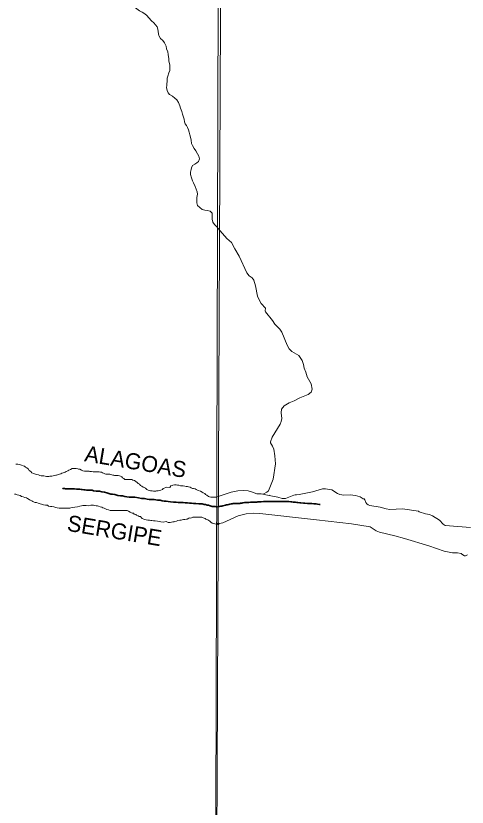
# Model space of a CAD drawing. Extents: x 553962 to 842807, y 8883888 to 9032388.
# Drawn here: x 595557 to 597811, y 8902976 to 8906931 of the extents above; entities that cross this region are included whole.
import ezdxf
from ezdxf.enums import TextEntityAlignment as Align

# ---------------------------------------------------------------- set-up
doc = ezdxf.new("R2010")
doc.units = 0
doc.header["$LTSCALE"] = 20
doc.header["$PDMODE"] = 32
doc.header["$PDSIZE"] = 10
doc.linetypes.add('LONG_DASH_SHORT_DASH', pattern=[9.9, 6, -1.2, 1.5, -1.2])
doc.layers.add('6', color=7, linetype='Continuous', lineweight=13)

msp = doc.modelspace()

# ---------------------------------------------------------------- linework, layer by layer
at = {"layer": '6'}
msp.add_line((597009.34, 8905170.59), (597009.47, 8905170.48), dxfattribs=at)
for points in [[(596655.53, 8924715.82), (596593.31, 8909930.27), (596531.66, 8896026.67)], [(596271.31, 8906832.67), (596268.84, 8906840.55), (596267.4, 8906852.57), (596265.95, 8906863.59), (596262.5, 8906875.62), (596254.54, 8906886.17), (596246.07, 8906895.23), (596235.12, 8906906.3), (596222.17, 8906920.38), (596211.22, 8906932.45), (596201.25, 8906941.01), (596187.27, 8906949.09), (596175.29, 8906955.66), (596161.83, 8906966.24), (596149.85, 8906973.81), (596139.89, 8906984.37), (596128.44, 8906996.94), (596121.49, 8907009.99), (596118.04, 8907020.52), (596117.51, 8907024.23)], [(596279.74, 8906816.97), (596272.29, 8906829.53), (596271.31, 8906832.67)], [(596461.16, 8906005.39), (596461.24, 8906022.7), (596463.82, 8906039.2), (596463.38, 8906051.22), (596457.43, 8906065.27), (596453.49, 8906078.3), (596444.56, 8906095.36), (596439.11, 8906106.91), (596433.67, 8906120.95), (596429.75, 8906138.49), (596429.79, 8906149), (596432.86, 8906162), (596433.9, 8906171.5), (596439.46, 8906181.98), (596451, 8906189.93), (596461.04, 8906195.39), (596470.08, 8906202.35), (596474.15, 8906216.84), (596471.21, 8906229.37), (596464.25, 8906241.42), (596455.81, 8906255.98), (596447.86, 8906268.03), (596439.92, 8906282.59), (596434.46, 8906292.63), (596433.04, 8906308.65), (596429.1, 8906323.69), (596426.15, 8906335.22), (596422.71, 8906348.75), (596419.27, 8906361.78), (596413.82, 8906373.32), (596408.85, 8906382.36), (596403.39, 8906390.89), (596399.93, 8906400.42), (596396.99, 8906413.45), (596393.55, 8906428.99), (596389.6, 8906440.02), (596386.16, 8906452.55), (596379.72, 8906468.6), (596376.28, 8906481.63), (596368.85, 8906497.18), (596361.4, 8906511.24), (596351.43, 8906519.3), (596339.97, 8906529.37), (596323.99, 8906537.46), (596317.29, 8906546.27), (596312.87, 8906557.64), (596309.71, 8906572.8), (596310.97, 8906582.91), (596310.72, 8906590.58), (596312.78, 8906603.09), (596313.36, 8906618.6), (596316.91, 8906629.09), (596321.49, 8906645.08), (596325.55, 8906657.57), (596326.12, 8906673.59), (596325.68, 8906686.1), (596321.76, 8906703.64), (596321.31, 8906715.66), (596317.41, 8906737.2), (596316.47, 8906750.72), (596310.03, 8906765.77), (596307.1, 8906779.79), (596300.17, 8906796.35), (596291.21, 8906807.91), (596279.74, 8906816.97)], [(596838.8, 8905408.88), (596804.04, 8905452.18), (596802.59, 8905456.77), (596803.35, 8905469.92), (596782.84, 8905493.91), (596770.59, 8905515.48), (596764.74, 8905530.23), (596754.34, 8905581.41), (596745.9, 8905609.64), (596737.38, 8905621.24), (596722.76, 8905631.69), (596710.55, 8905646.03), (596672.05, 8905729.1), (596650.19, 8905765.77), (596633.55, 8905797.37), (596611.19, 8905818.62), (596577.44, 8905855.54), (596559.67, 8905877.53), (596548.71, 8905888.6), (596540.25, 8905900.15), (596538.31, 8905914.18), (596537.89, 8905930.7), (596537.46, 8905945.22), (596526.99, 8905955.28), (596513.49, 8905957.86), (596500.49, 8905959.43), (596486.99, 8905962.5), (596476.02, 8905972.57), (596464.56, 8905983.14), (596461.12, 8905995.67), (596461.16, 8906005.39)], [(596792.7, 8904540.08), (596811.38, 8904551.14), (596818.41, 8904557.45), (596822.73, 8904565.46), (596841.54, 8904615.86), (596853.21, 8904691.81), (596850.74, 8904732.66), (596845.07, 8904764.51), (596839.3, 8904780.99), (596829.44, 8904796.54), (596828.87, 8904802.18), (596837.09, 8904824.68), (596877.08, 8904890.71), (596882.77, 8904903.43), (596885.53, 8904918.02), (596882.53, 8904946.28), (596884.25, 8904964.46), (596897.92, 8904981.99), (596922.55, 8904996.59), (596946.53, 8905006.22), (596975.28, 8905021.53), (597017.52, 8905037.76), (597031.77, 8905049.37), (597036.99, 8905064.96), (597032.35, 8905091.89), (597011.38, 8905127.44), (597004.88, 8905150.7), (596996.68, 8905170.37), (596994.07, 8905188.62), (596987.26, 8905207.98), (596969.76, 8905233.97), (596935.36, 8905253.15), (596921.53, 8905266.14), (596912.19, 8905285.14), (596886.01, 8905350.51), (596875.37, 8905364.73), (596850.41, 8905390.03), (596838.8, 8905408.88)], [(595556.5, 8904690.45), (595567.5, 8904689.88), (595574.99, 8904688.33), (595585.47, 8904685.25), (595592.96, 8904682.7), (595599.94, 8904679.65), (595605.91, 8904675.61), (595612.38, 8904672.06), (595619.84, 8904665.5), (595623.28, 8904657.97), (595631.75, 8904653.4), (595637.21, 8904647.36), (595645.68, 8904643.3), (595654.66, 8904639.73), (595659.65, 8904638.2), (595669.64, 8904637.13), (595677.62, 8904633.57), (595684.11, 8904631.53)], [(595684.11, 8904631.53), (595696.62, 8904631.94), (595710.6, 8904628.35), (595718.11, 8904629.3), (595722.11, 8904629.27), (595726.61, 8904629.74), (595733.12, 8904629.7), (595737.12, 8904630.17), (595744.14, 8904632.13), (595751.65, 8904633.08), (595756.16, 8904634.56), (595760.68, 8904636.03), (595765.19, 8904637), (595769.2, 8904638.97), (595774.72, 8904640.44), (595781.23, 8904642.4), (595786.76, 8904645.37), (595793.27, 8904646.33), (595802.8, 8904650.27), (595807.83, 8904653.74), (595816.86, 8904657.19), (595821.39, 8904660.66), (595830.42, 8904663.61), (595838.95, 8904668.06), (595844.96, 8904668.02), (595849.96, 8904667.98), (595857.96, 8904667.93), (595865.96, 8904667.38), (595870.45, 8904665.84), (595877.45, 8904664.8), (595884.91, 8904659.74), (595891.39, 8904656.19), (595899.39, 8904656.14), (595903.39, 8904656.11), (595910.89, 8904656.06), (595914.9, 8904656.04), (595922.89, 8904654.98), (595927.39, 8904654.45), (595934.89, 8904653.9), (595943.38, 8904652.34), (595951.38, 8904652.29), (595956.39, 8904652.26), (595963.39, 8904652.21), (595973.39, 8904651.64), (595980.39, 8904651.1), (595984.88, 8904650.57), (595989.36, 8904647.53), (595995.35, 8904645.99), (596002.33, 8904641.94), (596006.81, 8904639.91), (596012.82, 8904639.87), (596025.82, 8904639.78), (596041.29, 8904635.17), (596045.79, 8904634.64), (596050.28, 8904633.61), (596056.28, 8904633.07), (596063.79, 8904633.02), (596067.79, 8904632.99), (596074.29, 8904632.45), (596079.27, 8904630.41), (596086.25, 8904626.86), (596090.22, 8904622.33), (596097.2, 8904619.28), (596100.66, 8904614.25), (596107.15, 8904613.21), (596113.66, 8904613.16), (596120.66, 8904613.12), (596124.66, 8904613.09), (596128.66, 8904613.06), (596136.17, 8904613.01), (596142.15, 8904610.97), (596149.64, 8904608.42), (596156.11, 8904604.37), (596163.57, 8904599.31), (596168.03, 8904593.28), (596174.51, 8904590.23), (596180.46, 8904583.68), (596186.94, 8904580.13), (596193.41, 8904576.08), (596197.9, 8904574.05), (596204.37, 8904570), (596211.32, 8904563.45), (596217.3, 8904560.4), (596222.79, 8904558.87), (596229.78, 8904557.32), (596238.78, 8904556.26), (596245.28, 8904556.21), (596249.28, 8904556.19), (596255.79, 8904556.14), (596260.29, 8904556.61), (596268.3, 8904557.56), (596272.82, 8904559.04), (596280.83, 8904560.99), (596288.86, 8904564.44), (596292.89, 8904567.92), (596298.42, 8904570.88), (596306.95, 8904574.33), (596311.96, 8904575.3), (596326.95, 8904573.2), (596331.52, 8904582.68), (596337.54, 8904584.14)], [(596337.54, 8904584.14), (596341.55, 8904585.62), (596350.06, 8904586.56), (596357.56, 8904586.51), (596364.56, 8904585.97), (596371.06, 8904585.92), (596379.54, 8904581.86), (596386.54, 8904581.32), (596393.54, 8904581.27), (596401.54, 8904580.72), (596408.03, 8904579.17), (596414.02, 8904578.13), (596419.01, 8904576.59), (596427.01, 8904575.54), (596431.99, 8904572.5), (596439.97, 8904569.45), (596444.46, 8904567.91), (596451.95, 8904566.86), (596457.43, 8904563.32), (596468.4, 8904558.24), (596478.87, 8904554.67), (596487.34, 8904550.11), (596492.32, 8904546.57), (596500.29, 8904543.01), (596504.26, 8904538.98), (596511.74, 8904535.42), (596519.2, 8904529.37), (596523.69, 8904527.83), (596531.68, 8904525.78), (596538.17, 8904524.73), (596545.18, 8904524.69), (596549.18, 8904524.66), (596554.18, 8904525.13), (596558.18, 8904525.1), (596568.11, 8904529.4), (596633.02, 8904549.67), (596665.53, 8904556.47), (596692.28, 8904558.41), (596717.2, 8904556.97), (596733.78, 8904552.43)], [(596822.73, 8904565.46), (596818.41, 8904557.45), (596811.38, 8904551.14), (596792.7, 8904540.08)], [(596823.34, 8904534.56), (596822.94, 8904534.26), (596866.14, 8904524.62), (596887.51, 8904518.14), (596904.41, 8904518.5), (596944.71, 8904535.19), (596952.22, 8904537.44), (596959.17, 8904537.7), (596972.2, 8904538.73), (597038.54, 8904552.33), (597088.86, 8904566.91), (597103.45, 8904567.82), (597135.08, 8904562.23), (597163.29, 8904544.38), (597175.46, 8904538.55), (597195.15, 8904535.8), (597227.31, 8904537.41), (597253.94, 8904534.12), (597277.12, 8904527.29), (597291.87, 8904517.36), (597296.94, 8904516.65), (597300.57, 8904511.31), (597305.06, 8904499.07), (597310.04, 8904491.83), (597315.94, 8904486.58), (597325.36, 8904483.16), (597377.15, 8904474.75), (597406.82, 8904466.62), (597425.39, 8904464.55), (597487.99, 8904467), (597567.88, 8904454.89)], [(596112.98, 8904457.95), (596105.98, 8904458.5), (596097.48, 8904459.05), (596092.48, 8904459.09), (596084.47, 8904459.14), (596079.47, 8904459.17), (596067.47, 8904459.25), (596056.96, 8904459.32), (596049.96, 8904459.37), (596041.96, 8904459.42), (596036.45, 8904459.46), (596027.95, 8904459.51), (596019.97, 8904462.57), (596011.98, 8904463.62), (596005, 8904467.68), (595998.52, 8904470.72), (595991.54, 8904472.77), (595987.06, 8904475.81), (595977.56, 8904476.87), (595969.58, 8904479.93), (595965.09, 8904481.46), (595958.59, 8904482.5), (595950.1, 8904484.06), (595945.11, 8904485.1), (595936.61, 8904485.15), (595932.1, 8904485.18), (595920.08, 8904482.26), (595908.58, 8904483.34), (595897.58, 8904483.41), (595892.07, 8904482.94), (595885.06, 8904481.99), (595877.04, 8904480.54), (595865.01, 8904477.11), (595851, 8904476.21), (595840.47, 8904473.27), (595832.46, 8904471.82), (595826.95, 8904470.86), (595816.44, 8904470.43), (595808.44, 8904470.48), (595798.43, 8904470.54), (595789.43, 8904470.6), (595783.93, 8904470.64), (595773.92, 8904470.71), (595763.93, 8904472.28), (595756.94, 8904473.82), (595746.96, 8904477.39), (595736.96, 8904477.96), (595730.47, 8904479.51), (595720.98, 8904481.07), (595715.5, 8904484.61), (595704.51, 8904485.69), (595695.02, 8904487.25), (595684.53, 8904490.33), (595678.04, 8904491.87), (595669.06, 8904494.93), (595661.08, 8904497.99), (595653.59, 8904499.04), (595649.1, 8904500.57), (595642.62, 8904503.62), (595637.64, 8904507.16), (595628.66, 8904510.22), (595623.68, 8904513.26), (595615.22, 8904518.32), (595609.74, 8904521.86), (595601.75, 8904522.92), (595593.27, 8904526.98), (595585.79, 8904529.53), (595579.32, 8904533.58), (595571.33, 8904536.14), (595563.84, 8904537.69), (595557.35, 8904539.74), (595550.36, 8904540.78)], [(596733.78, 8904552.43), (596760.36, 8904542.11), (596781.9, 8904541.65), (596822.94, 8904534.26)], [(596137.89, 8904445.27), (596128.43, 8904450.84), (596120.46, 8904454.9), (596112.98, 8904457.95)], [(596412.79, 8904415.91), (596408.79, 8904415.94), (596401.27, 8904414.48), (596394.26, 8904413.03), (596387.24, 8904411.57), (596383.23, 8904410.6), (596376.23, 8904409.64), (596366.71, 8904408.2), (596360.18, 8904405.24), (596351.17, 8904404.3), (596347.16, 8904402.82), (596341.15, 8904401.86), (596335.13, 8904399.9), (596328.62, 8904398.94), (596324.12, 8904398.47), (596317.11, 8904398.52), (596307.15, 8904403.59), (596293.12, 8904401.18), (596281.13, 8904402.26), (596273.13, 8904403.81), (596264.64, 8904405.37), (596253.65, 8904406.45), (596244.65, 8904407.51), (596236.65, 8904408.06), (596232.16, 8904409.09), (596224.16, 8904410.15), (596216.67, 8904411.2), (596208.68, 8904412.75), (596201.18, 8904414.3), (596196.19, 8904415.84), (596188.71, 8904418.89), (596184.24, 8904422.93), (596179.28, 8904427.97), (596173.28, 8904429.01), (596167.8, 8904432.05), (596160.32, 8904435.1), (596155.85, 8904438.64), (596148.85, 8904439.69), (596144.89, 8904444.72), (596137.89, 8904445.27)], [(597784.49, 8904240.95), (597780.81, 8904243.47), (597763.03, 8904246.89), (597737.67, 8904248), (597696.38, 8904255.69), (597619.92, 8904282.06), (597498.2, 8904319.56), (597449.97, 8904332.91), (597372.55, 8904350.27), (597356, 8904357.65), (597326.45, 8904376.33), (597232.92, 8904391.82), (597058.07, 8904411.64), (596775.07, 8904444.07), (596742.38, 8904446.03), (596707.45, 8904442.77), (596667.39, 8904431.58), (596590.07, 8904397.56), (596568.11, 8904391.54), (596558.66, 8904389.91), (596551.16, 8904391.46), (596544.18, 8904394.01), (596537.69, 8904395.55), (596530.73, 8904401.11), (596526.25, 8904404.64), (596520.29, 8904409.19), (596515.81, 8904412.22), (596506.83, 8904415.79), (596502.35, 8904419.32), (596492.37, 8904422.39), (596485.39, 8904425.44), (596475.89, 8904426.01), (596467.39, 8904426.06), (596458.39, 8904426.12), (596449.38, 8904426.18), (596440.37, 8904425.24), (596431.84, 8904421.29), (596424.84, 8904421.34), (596420.32, 8904419.86), (596412.79, 8904415.91)], [(597567.88, 8904454.89), (597572.2, 8904452.58), (597602.59, 8904441.55), (597622.94, 8904438.16), (597637.95, 8904432.9), (597672.15, 8904410.22), (597691.38, 8904390.61), (597701.66, 8904384.27), (597826.91, 8904374.26)], [(597812.2, 8904237.92), (597802.87, 8904232.5), (597797.61, 8904231.95), (597784.49, 8904240.95)]]:
    msp.add_lwpolyline(points, dxfattribs=at)
msp.add_lwpolyline([(596575.77, 8909932.4), (585614.83, 8909969.81), (585583.82, 8898914.37), (596544.75, 8898874.89)], close=True, dxfattribs=at)
at = {"layer": '6', "linetype": 'LONG_DASH_SHORT_DASH', "lineweight": 35}
for points in [[(596403.14, 8904497.57), (596393.14, 8904498.13), (596385.15, 8904498.67), (596380.15, 8904498.7), (596375.15, 8904499.22), (596367.15, 8904499.27), (596358.65, 8904499.81), (596344.16, 8904500.89), (596330.17, 8904501.96), (596318.18, 8904504.53), (596307.19, 8904505.09), (596298.19, 8904506.14), (596288.7, 8904507.19), (596278.22, 8904509.75), (596264.22, 8904510.32), (596247.24, 8904512.91), (596234.74, 8904512.98), (596223.24, 8904513.54), (596212.25, 8904514.6), (596200.27, 8904518.17), (596185.28, 8904519.25), (596169.8, 8904521.83), (596151.32, 8904524.93), (596136.32, 8904525.01), (596122.82, 8904526.08), (596111.83, 8904527.14), (596101.34, 8904528.2), (596090.36, 8904531.26), (596079.36, 8904531.82), (596065.88, 8904534.39), (596051.9, 8904537.97), (596040.42, 8904540.53), (596030.92, 8904541.08), (596021.44, 8904543.64), (596011.96, 8904546.69), (595999.98, 8904549.75), (595987, 8904552.83), (595974.52, 8904555.4), (595957.52, 8904555.99), (595944.53, 8904557.06), (595937.55, 8904559.59), (595929.54, 8904559.64), (595924.04, 8904559.67), (595915.55, 8904560.21), (595909.55, 8904560.74), (595903.06, 8904561.78), (595897.06, 8904562.31), (595889.07, 8904563.86), (595883.08, 8904564.39), (595877.08, 8904564.92), (595870.09, 8904565.96), (595860.59, 8904566.01), (595850.09, 8904566.56), (595840.59, 8904567.11), (595830.09, 8904567.17), (595819.09, 8904567.23), (595811.1, 8904567.77), (595805.6, 8904567.8), (595800.1, 8904568.83), (595791.61, 8904569.38), (595790.22, 8904569.73)], [(596572.95, 8904478.68), (596563.99, 8904475.2), (596553.01, 8904478.26), (596546.02, 8904478.8), (596537.02, 8904479.35), (596527.04, 8904481.9), (596519.56, 8904484.95), (596512.07, 8904485.99), (596504.58, 8904488.53), (596497.09, 8904489.57), (596487.6, 8904492.12), (596479.1, 8904492.17), (596471.61, 8904492.71), (596456.61, 8904493.29), (596443.61, 8904493.86), (596434.12, 8904494.91), (596425.12, 8904495.46), (596414.63, 8904496.51), (596403.14, 8904497.57)], [(597057.41, 8904491.98), (597045.71, 8904492.49), (597036.04, 8904494.02), (597030.44, 8904494.02), (597021.79, 8904494.54), (597014.16, 8904494.54), (597000.42, 8904495.56), (596993.29, 8904496.07), (596981.08, 8904496.58), (596974.97, 8904497.6), (596965.81, 8904498.11), (596961.23, 8904498.11), (596954.11, 8904499.65), (596950.03, 8904500.16), (596942.91, 8904500.67), (596935.28, 8904501.69), (596929.68, 8904502.71), (596920.01, 8904503.74), (596907.29, 8904503.73), (596895.58, 8904503.73), (596889.98, 8904503.73), (596880.31, 8904503.73), (596874.21, 8904503.73), (596857.92, 8904503.73), (596850.8, 8904503.73), (596839.09, 8904503.73), (596832.99, 8904503.73), (596821.79, 8904503.73), (596815.68, 8904503.73), (596801.44, 8904503.73), (596793.8, 8904503.73), (596782.1, 8904502.71), (596775.99, 8904502.2), (596765.81, 8904501.69), (596760.73, 8904500.67), (596750.55, 8904499.64), (596741.9, 8904499.64), (596737.32, 8904499.64), (596728.67, 8904499.64), (596720.52, 8904498.62), (596710.85, 8904498.62), (596699.66, 8904498.11), (596691.01, 8904496.57), (596686.43, 8904496.06), (596679.3, 8904495.55), (596675.23, 8904494.53), (596665.56, 8904494.02), (596659.46, 8904494.02), (596654.37, 8904494.02), (596648.77, 8904494.02), (596642.66, 8904494.02), (596637.07, 8904492.48), (596633, 8904492.48), (596625.87, 8904490.44), (596620.27, 8904489.42), (596614.68, 8904487.88), (596608.57, 8904486.35), (596603.48, 8904484.81), (596597.38, 8904483.79), (596591.27, 8904482.26), (596585.16, 8904480.72), (596579.06, 8904479.7), (596572.95, 8904478.68), (596572.95, 8904478.68), (596572.95, 8904478.68)], [(597076.6, 8904488.78), (597073.7, 8904489.42), (597063.01, 8904490.45), (597057.41, 8904491.98)]]:
    msp.add_lwpolyline(points, dxfattribs=at)
at = {"layer": '6'}
msp.add_point((596568.11, 8904391.54), dxfattribs=at)

# ---------------------------------------------------------------- texts
for s, p in [('ALAGOAS', (596148.89, 8904663.42)), ('SERGIPE', (596043.62, 8904318.97))]:
    msp.add_text(s, height=80, rotation=350.533, dxfattribs=at).set_placement(p, align=Align.CENTER)

doc.saveas('drawing.dxf')
